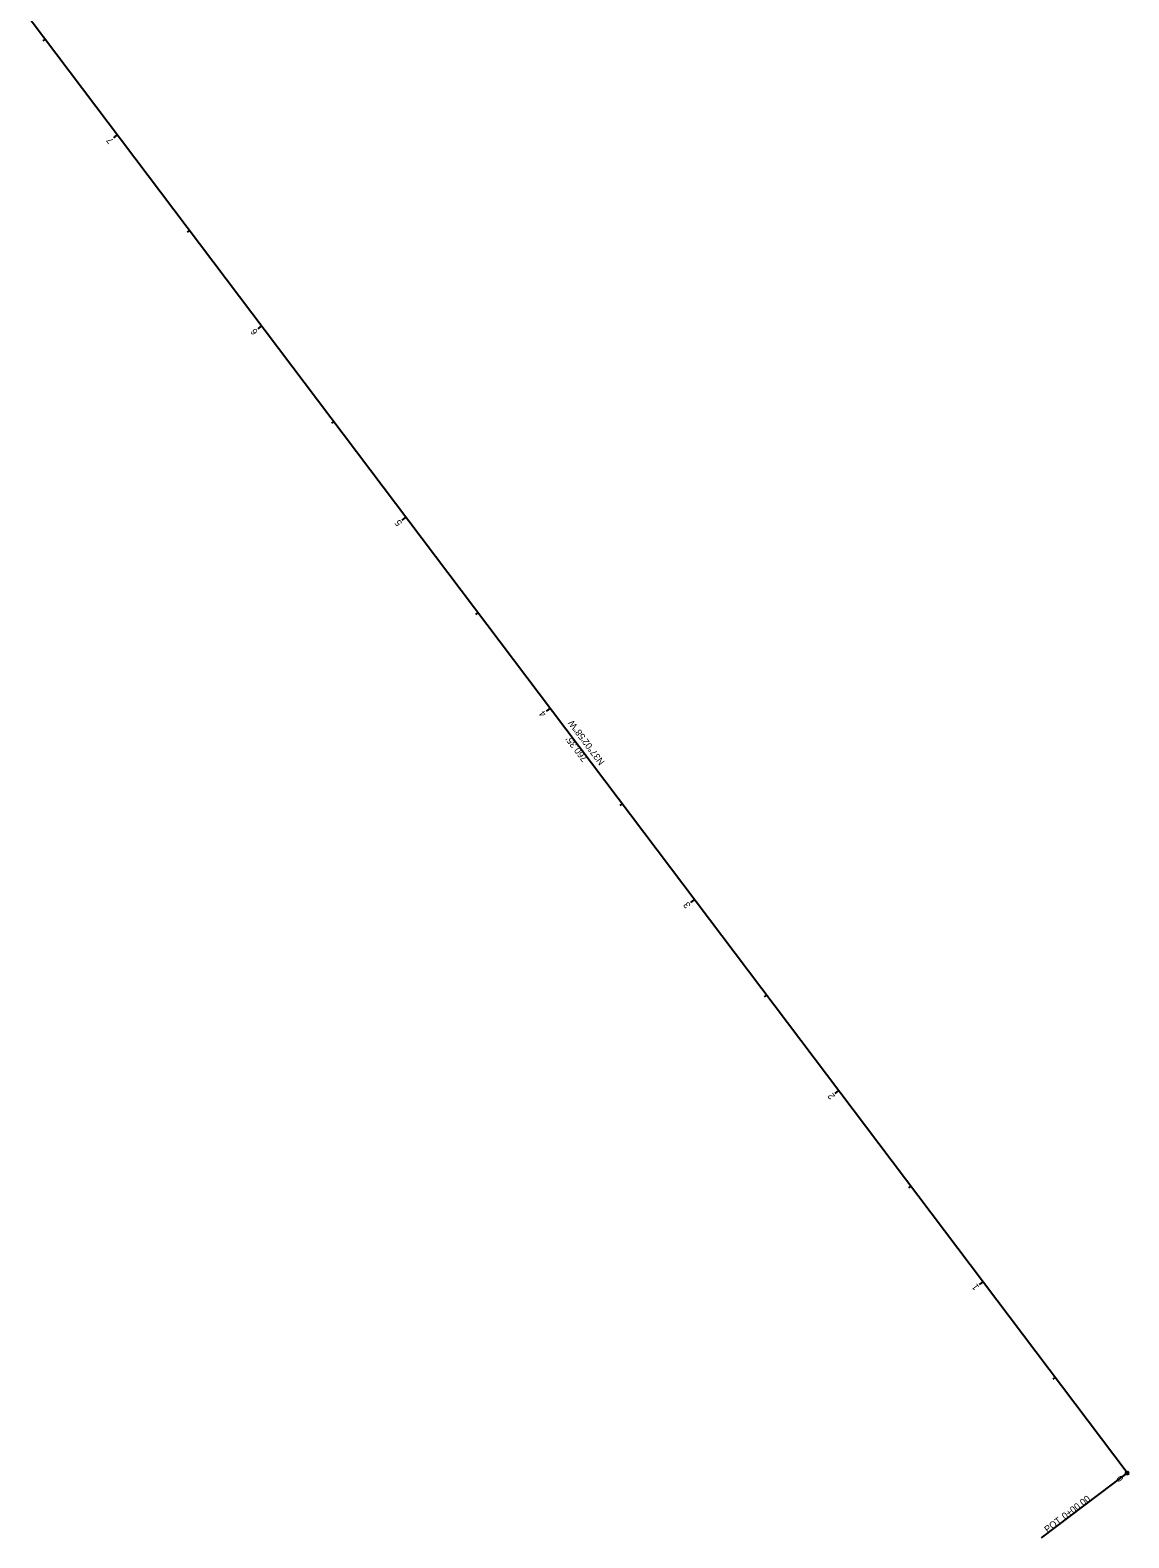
# Model space of a CAD drawing. Extents: x 1362949 to 1365618, y 484963 to 490440.
# Drawn here: x 1365159 to 1365618, y 484963 to 485593 of the extents above; entities that cross this region are included whole.
import ezdxf

# ---------------------------------------------------------------- set-up
doc = ezdxf.new("R2010")
doc.units = 0
for name, color, linetype in [('BR_X_SV_Bottom_of_Beam_Text', 7, 'Continuous'), ('BR_X_SV_Shot_Marker', 7, 'Continuous'), ('Default', 7, 'Continuous'), ('DR_X_Cells', 7, 'Continuous'), ('DR_X_Elev_Flow', 7, 'Continuous'), ('GK_Drainage_Nodes', 7, 'Continuous'), ('PV_X_Curb', 7, 'Continuous'), ('RD_X_GR_Rt', 7, 'Continuous'), ('SG_X_PullBox', 7, 'Continuous'), ('SV_P_Control_Cells_Set', 7, 'Continuous'), ('SV_X_Break_Lines', 7, 'Continuous'), ('UT_X_Electric', 7, 'Continuous'), ('UT_X_Sanitary_Cells', 7, 'Continuous'), ('UT_X_Unknown_Cells', 7, 'Continuous')]:
    doc.layers.add(name, color=color, linetype=linetype)

msp = doc.modelspace()

# ---------------------------------------------------------------- linework, layer by layer
at = {"layer": 'BR_X_SV_Bottom_of_Beam_Text'}
for p, q in [((1365165.56, 485588.81), (1365164.6, 485588.09)), ((1365195.68, 485548.9), (1365194.09, 485547.7)), ((1365225.81, 485509), (1365224.85, 485508.27)), ((1365255.93, 485469.09), (1365254.34, 485467.89)), ((1365286.06, 485429.19), (1365285.1, 485428.46)), ((1365316.18, 485389.28), (1365314.59, 485388.08)), ((1365346.31, 485349.37), (1365345.35, 485348.65)), ((1365376.43, 485309.47), (1365374.84, 485308.26)), ((1365406.56, 485269.56), (1365405.6, 485268.84)), ((1365436.68, 485229.66), (1365435.09, 485228.45)), ((1365466.81, 485189.75), (1365465.85, 485189.03)), ((1365496.93, 485149.85), (1365495.34, 485148.64)), ((1365527.06, 485109.94), (1365526.1, 485109.22)), ((1365557.18, 485070.03), (1365555.59, 485068.83)), ((1365587.31, 485030.13), (1365586.35, 485029.41)), ((1365617.43, 484990.22), (1365615.84, 484989.02))]:
    msp.add_line(p, q, dxfattribs=at)
at = {"layer": 'BR_X_SV_Shot_Marker'}
msp.add_line((1365617.43, 484990.22), (1365581.52, 484963.11), dxfattribs=at)
msp.add_circle((1365617.43, 484990.22), 0.6, dxfattribs=at)
at = {"layer": 'Default'}
for p, q in [((1365616.77, 484989.56), (1365618.1, 484990.89)), ((1365616.77, 484990.89), (1365618.1, 484989.56))]:
    msp.add_line(p, q, dxfattribs=at)
at = {"layer": 'PV_X_Curb'}
for p, q in [((1365195.68, 485548.9), (1365194.72, 485548.18)), ((1365255.93, 485469.09), (1365254.97, 485468.37)), ((1365316.18, 485389.28), (1365314.59, 485388.08)), ((1365376.43, 485309.47), (1365375.48, 485308.75)), ((1365436.68, 485229.66), (1365435.73, 485228.93)), ((1365496.93, 485149.85), (1365495.98, 485149.12)), ((1365557.18, 485070.03), (1365556.23, 485069.31)), ((1365617.43, 484990.22), (1365615.84, 484989.02))]:
    msp.add_line(p, q, dxfattribs=at)
at = {"layer": 'RD_X_GR_Rt'}
msp.add_line((1365617.43, 484990.22), (1365581.52, 484963.11), dxfattribs=at)
msp.add_circle((1365617.43, 484990.22), 0.6, dxfattribs=at)
at = {"layer": 'SG_X_PullBox'}
msp.add_line((1365617.43, 484990.22), (1365581.52, 484963.11), dxfattribs=at)
msp.add_circle((1365617.43, 484990.22), 0.6, dxfattribs=at)
at = {"layer": 'SV_X_Break_Lines'}
for p, q in [((1365316.18, 485389.28), (1365315.22, 485388.56)), ((1365617.43, 484990.22), (1365615.84, 484989.02))]:
    msp.add_line(p, q, dxfattribs=at)
at = {"layer": 'UT_X_Unknown_Cells'}
msp.add_line((1365617.43, 484990.22), (1365159.32, 485597.07), dxfattribs=at)

# ---------------------------------------------------------------- texts
at = {"layer": 'BR_X_SV_Bottom_of_Beam_Text'}
for s, p in [('7', (1365194.39, 485546.47)), ('6', (1365254.57, 485466.67)), ('5', (1365314.82, 485386.85)), ('4', (1365375.08, 485307.11)), ('3', (1365435.31, 485227.25)), ('2', (1365495.6, 485147.46)), ('1', (1365555.75, 485067.78)), ('0', (1365616.07, 484987.81))]:
    msp.add_text(s, height=2.8, rotation=127.0495, dxfattribs=at).set_placement(p)
at = {"layer": 'BR_X_SV_Shot_Marker'}
for s, p in [('0+00.00', (1365591.41, 484970.63)), ('POT', (1365584.12, 484965.13))]:
    msp.add_text(s, height=2.8, rotation=37.0495, dxfattribs=at).set_placement(p)
at = {"layer": 'DR_X_Cells'}
msp.add_text("760.35'", height=2.8, rotation=127.0495, dxfattribs=at).set_placement((1365392.25, 485288.44))
at = {"layer": 'DR_X_Elev_Flow'}
msp.add_text('N37°02\'58"W', height=2.8, rotation=127.0495, dxfattribs=at).set_placement((1365399.36, 485287.07))
at = {"layer": 'GK_Drainage_Nodes'}
msp.add_text("760.35'", height=2.8, rotation=127.0495, dxfattribs=at).set_placement((1365392.25, 485288.44))
at = {"layer": 'PV_X_Curb'}
for s, p in [('5', (1365314.82, 485386.85)), ('0', (1365616.07, 484987.81))]:
    msp.add_text(s, height=2.8, rotation=127.0495, dxfattribs=at).set_placement(p)
at = {"layer": 'RD_X_GR_Rt'}
for s, p in [('0+00.00', (1365591.41, 484970.63)), ('POT', (1365584.12, 484965.13))]:
    msp.add_text(s, height=2.8, rotation=37.0495, dxfattribs=at).set_placement(p)
at = {"layer": 'SG_X_PullBox'}
for s, p in [('0+00.00', (1365591.41, 484970.63)), ('POT', (1365584.12, 484965.13))]:
    msp.add_text(s, height=2.8, rotation=37.0495, dxfattribs=at).set_placement(p)
at = {"layer": 'SV_P_Control_Cells_Set'}
msp.add_text('N37°02\'58"W', height=2.8, rotation=127.0495, dxfattribs=at).set_placement((1365399.36, 485287.07))
at = {"layer": 'SV_X_Break_Lines'}
msp.add_text('0', height=2.8, rotation=127.0495, dxfattribs=at).set_placement((1365616.07, 484987.81))
at = {"layer": 'UT_X_Electric'}
msp.add_text('N37°02\'58"W', height=2.8, rotation=127.0495, dxfattribs=at).set_placement((1365399.36, 485287.07))
at = {"layer": 'UT_X_Sanitary_Cells'}
msp.add_text("760.35'", height=2.8, rotation=127.0495, dxfattribs=at).set_placement((1365392.25, 485288.44))

doc.saveas('drawing.dxf')
